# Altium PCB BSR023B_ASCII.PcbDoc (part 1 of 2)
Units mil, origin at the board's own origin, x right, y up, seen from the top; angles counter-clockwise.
Board outline 3000 x 3000 mil, 4 copper layers (Top Layer, MidLayer 1, Mid Layer 2, Bottom Layer), stack 59.2 mil thick; 96 components, 24 nets, 183 pads, 215 vias.
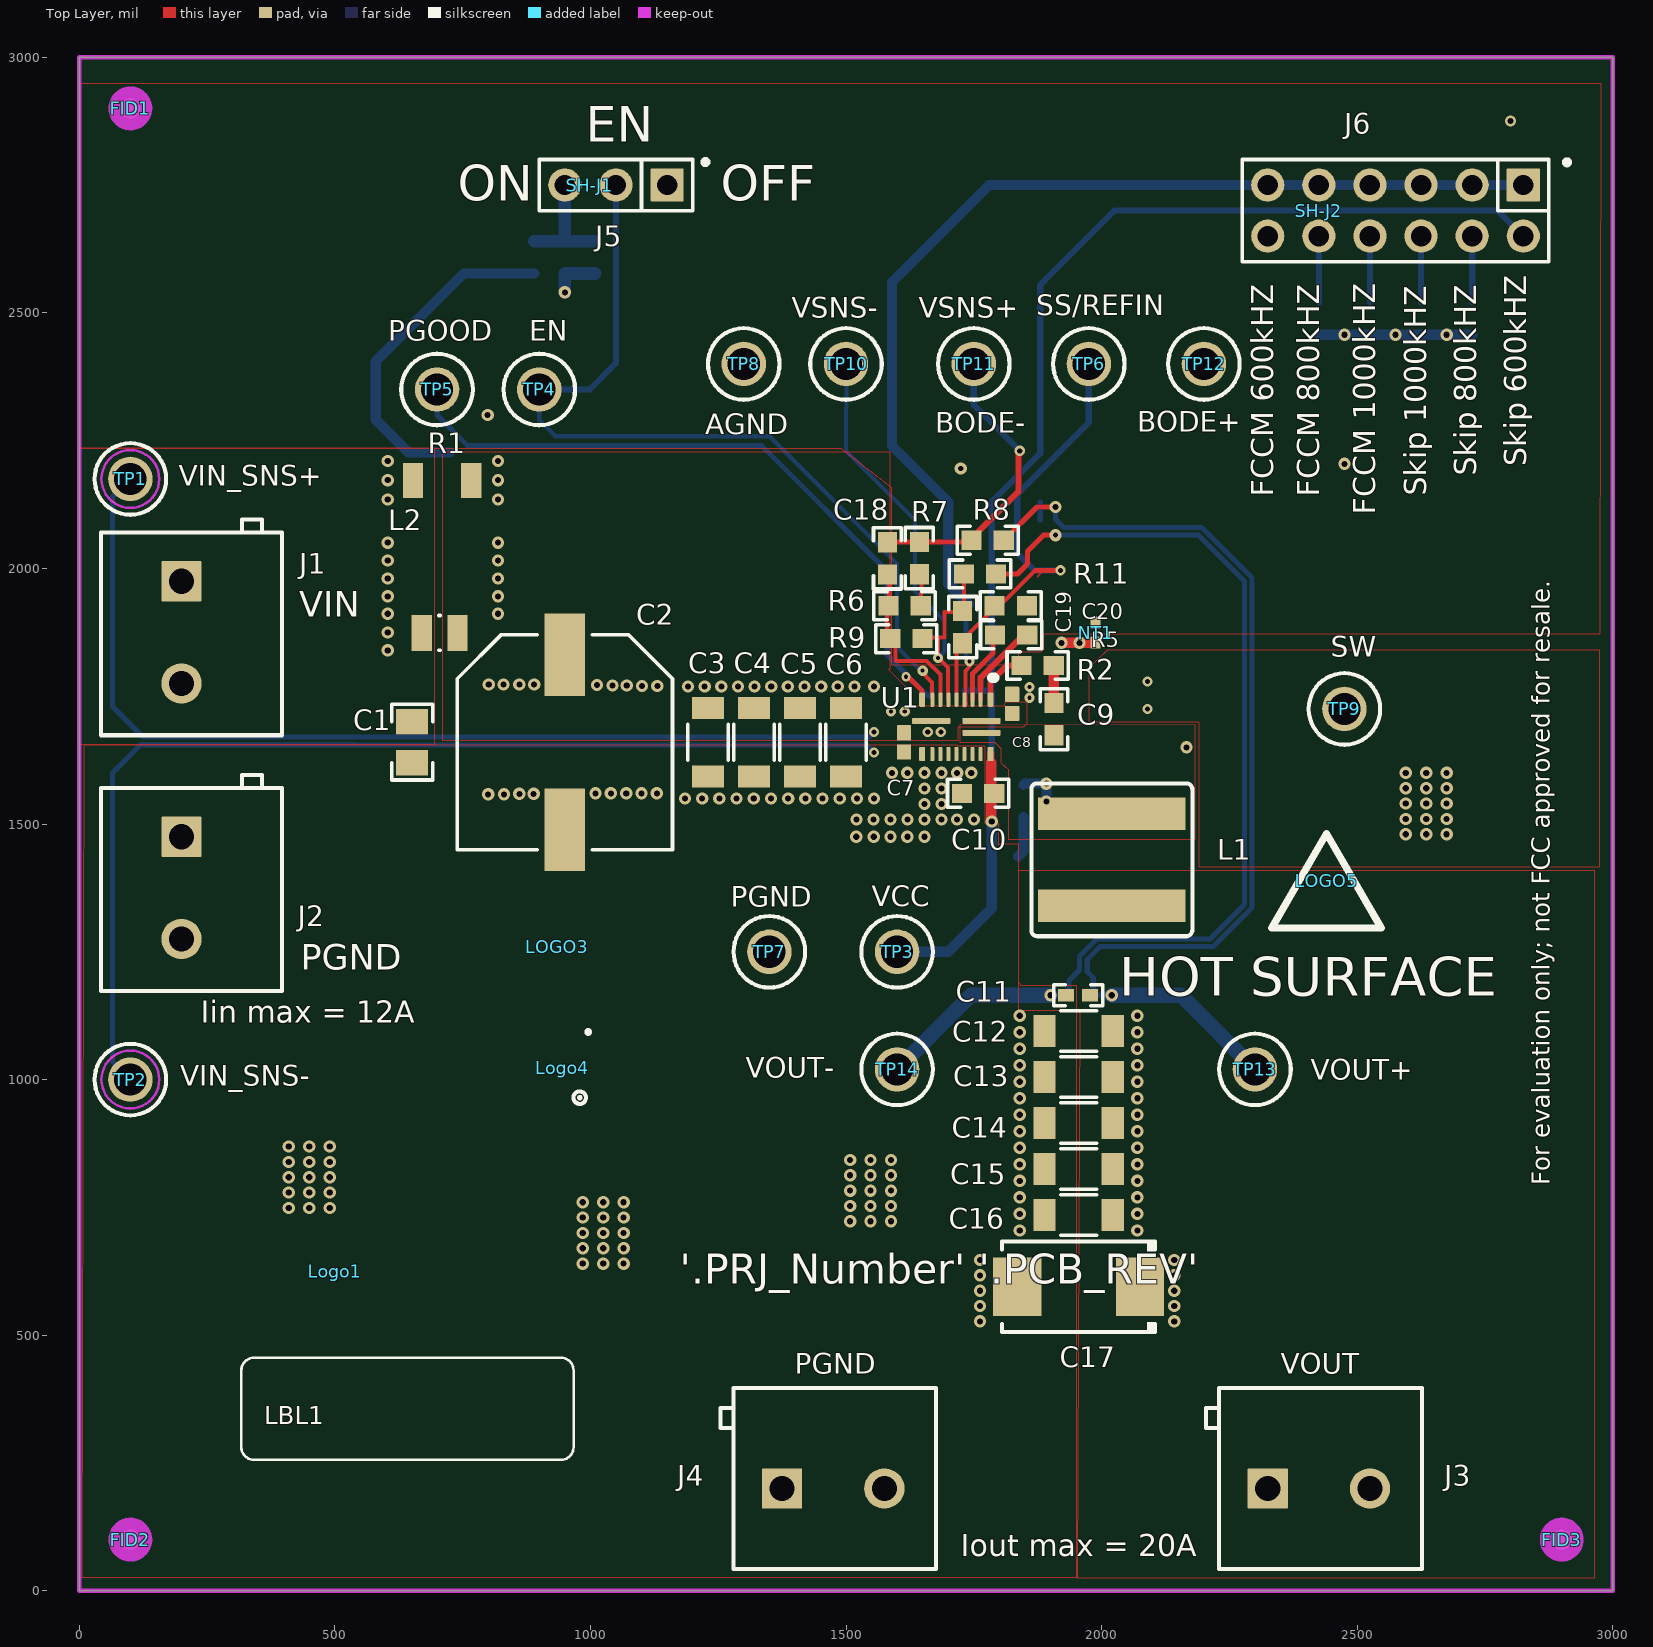
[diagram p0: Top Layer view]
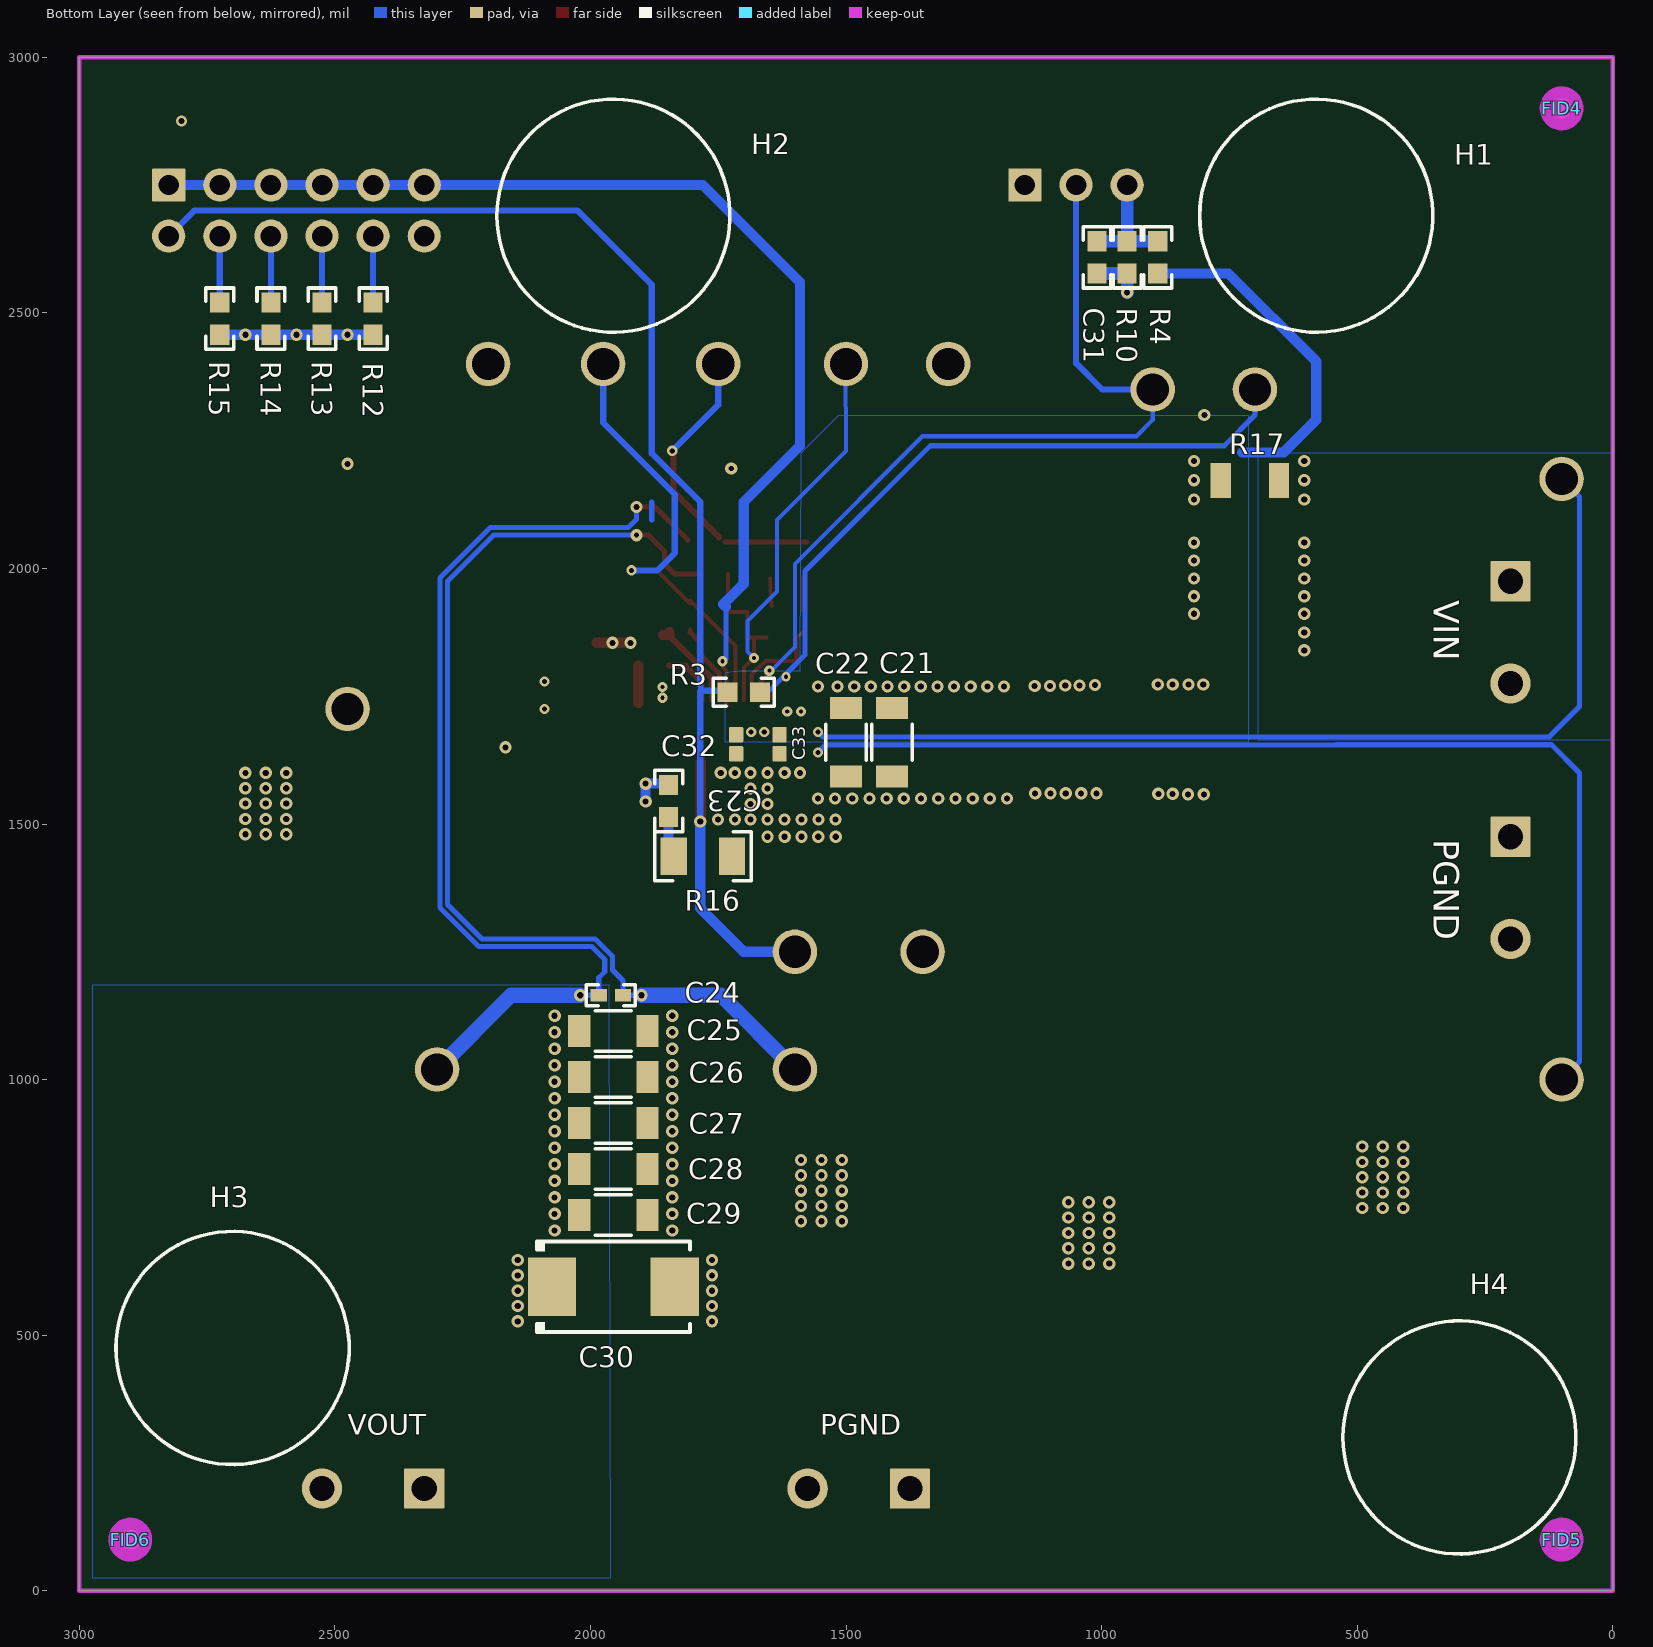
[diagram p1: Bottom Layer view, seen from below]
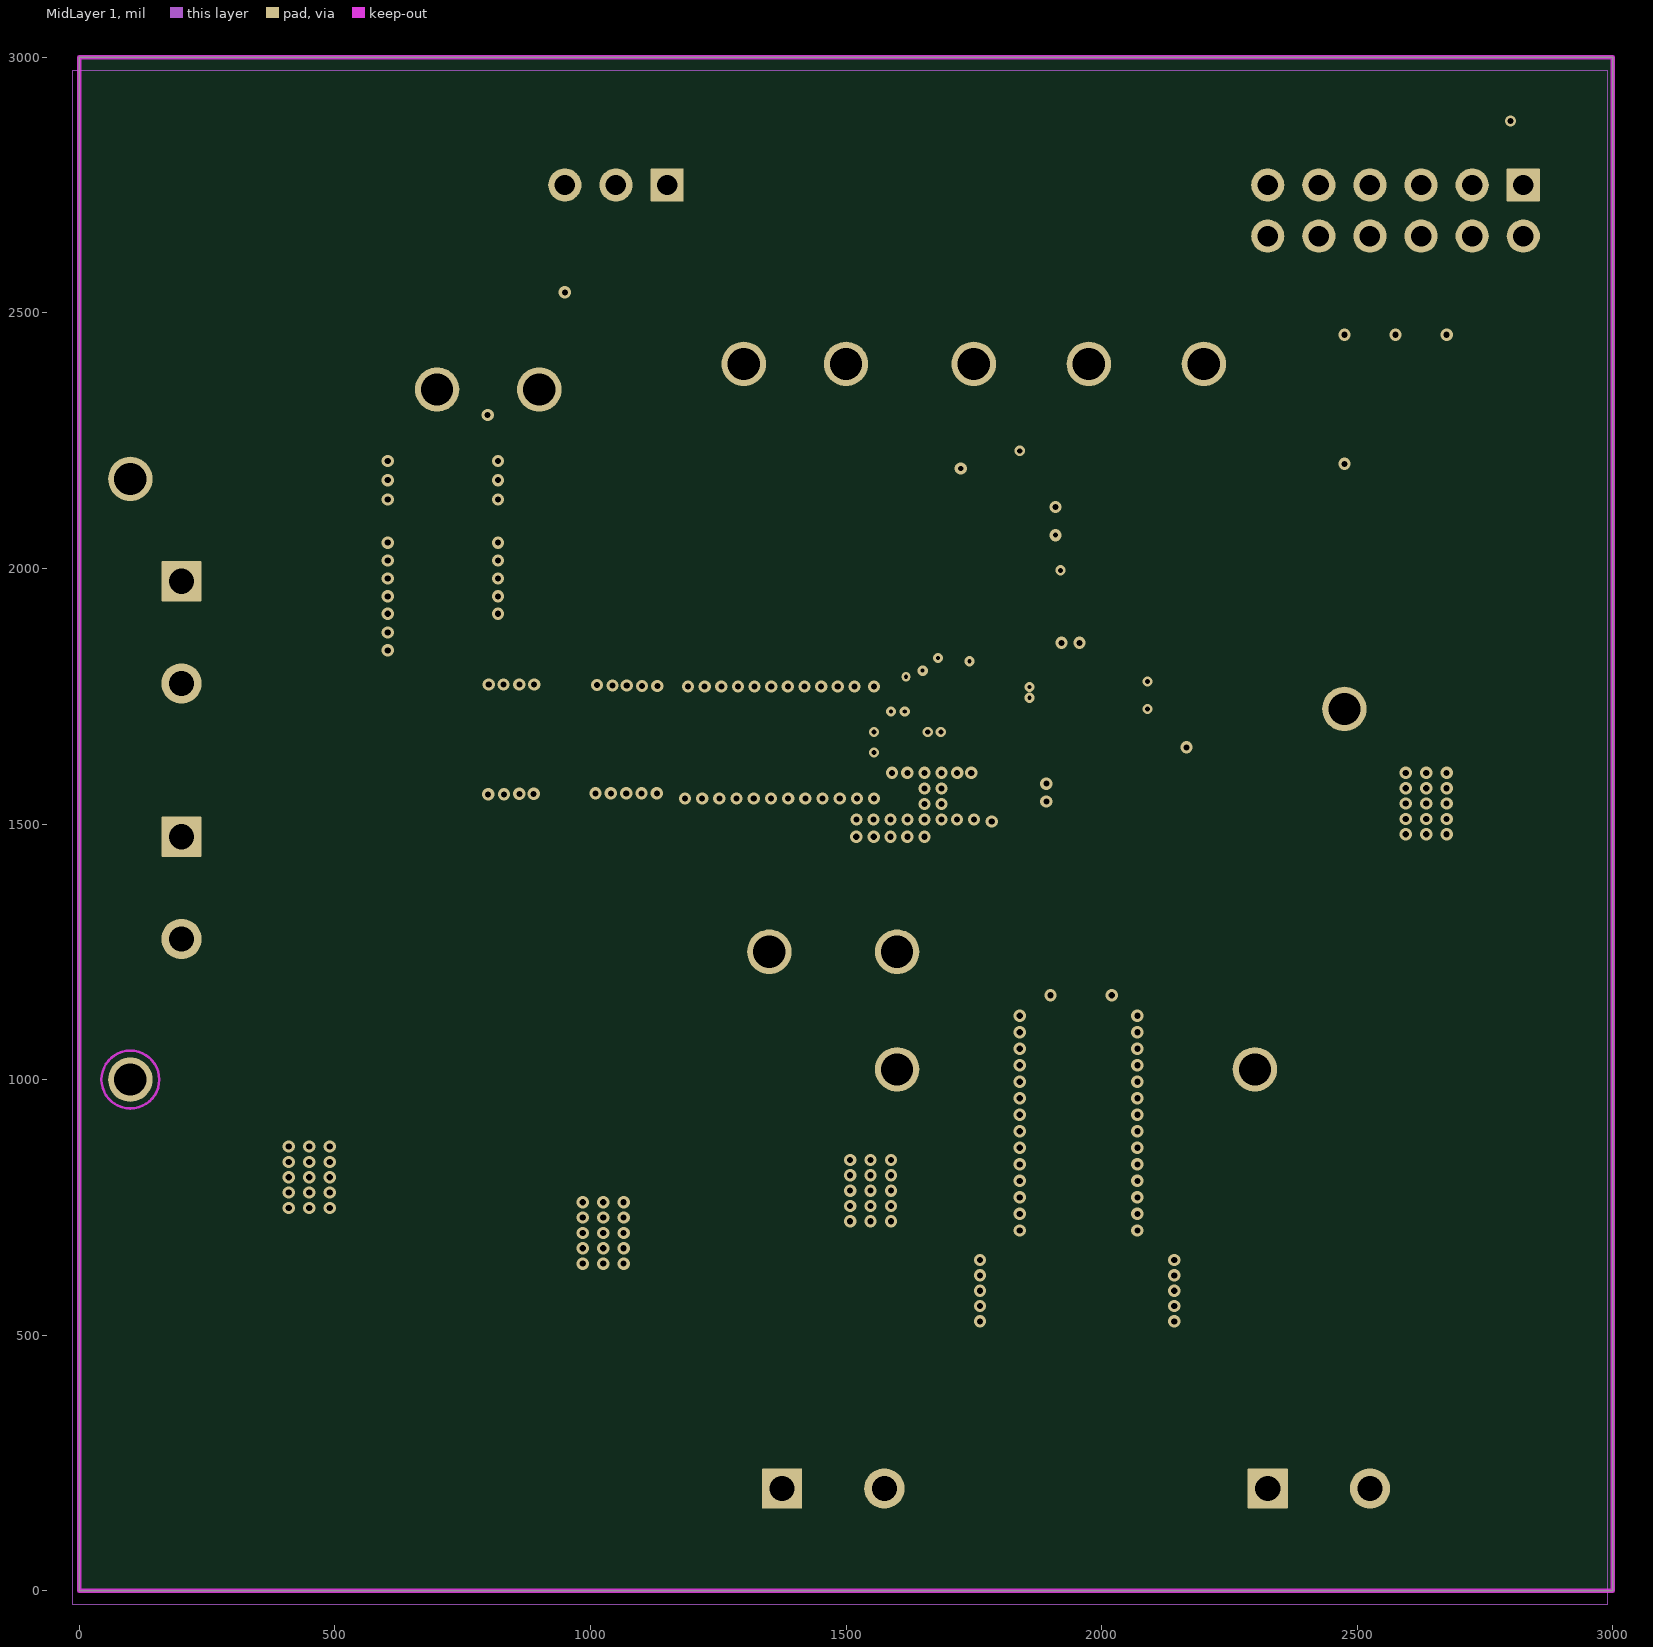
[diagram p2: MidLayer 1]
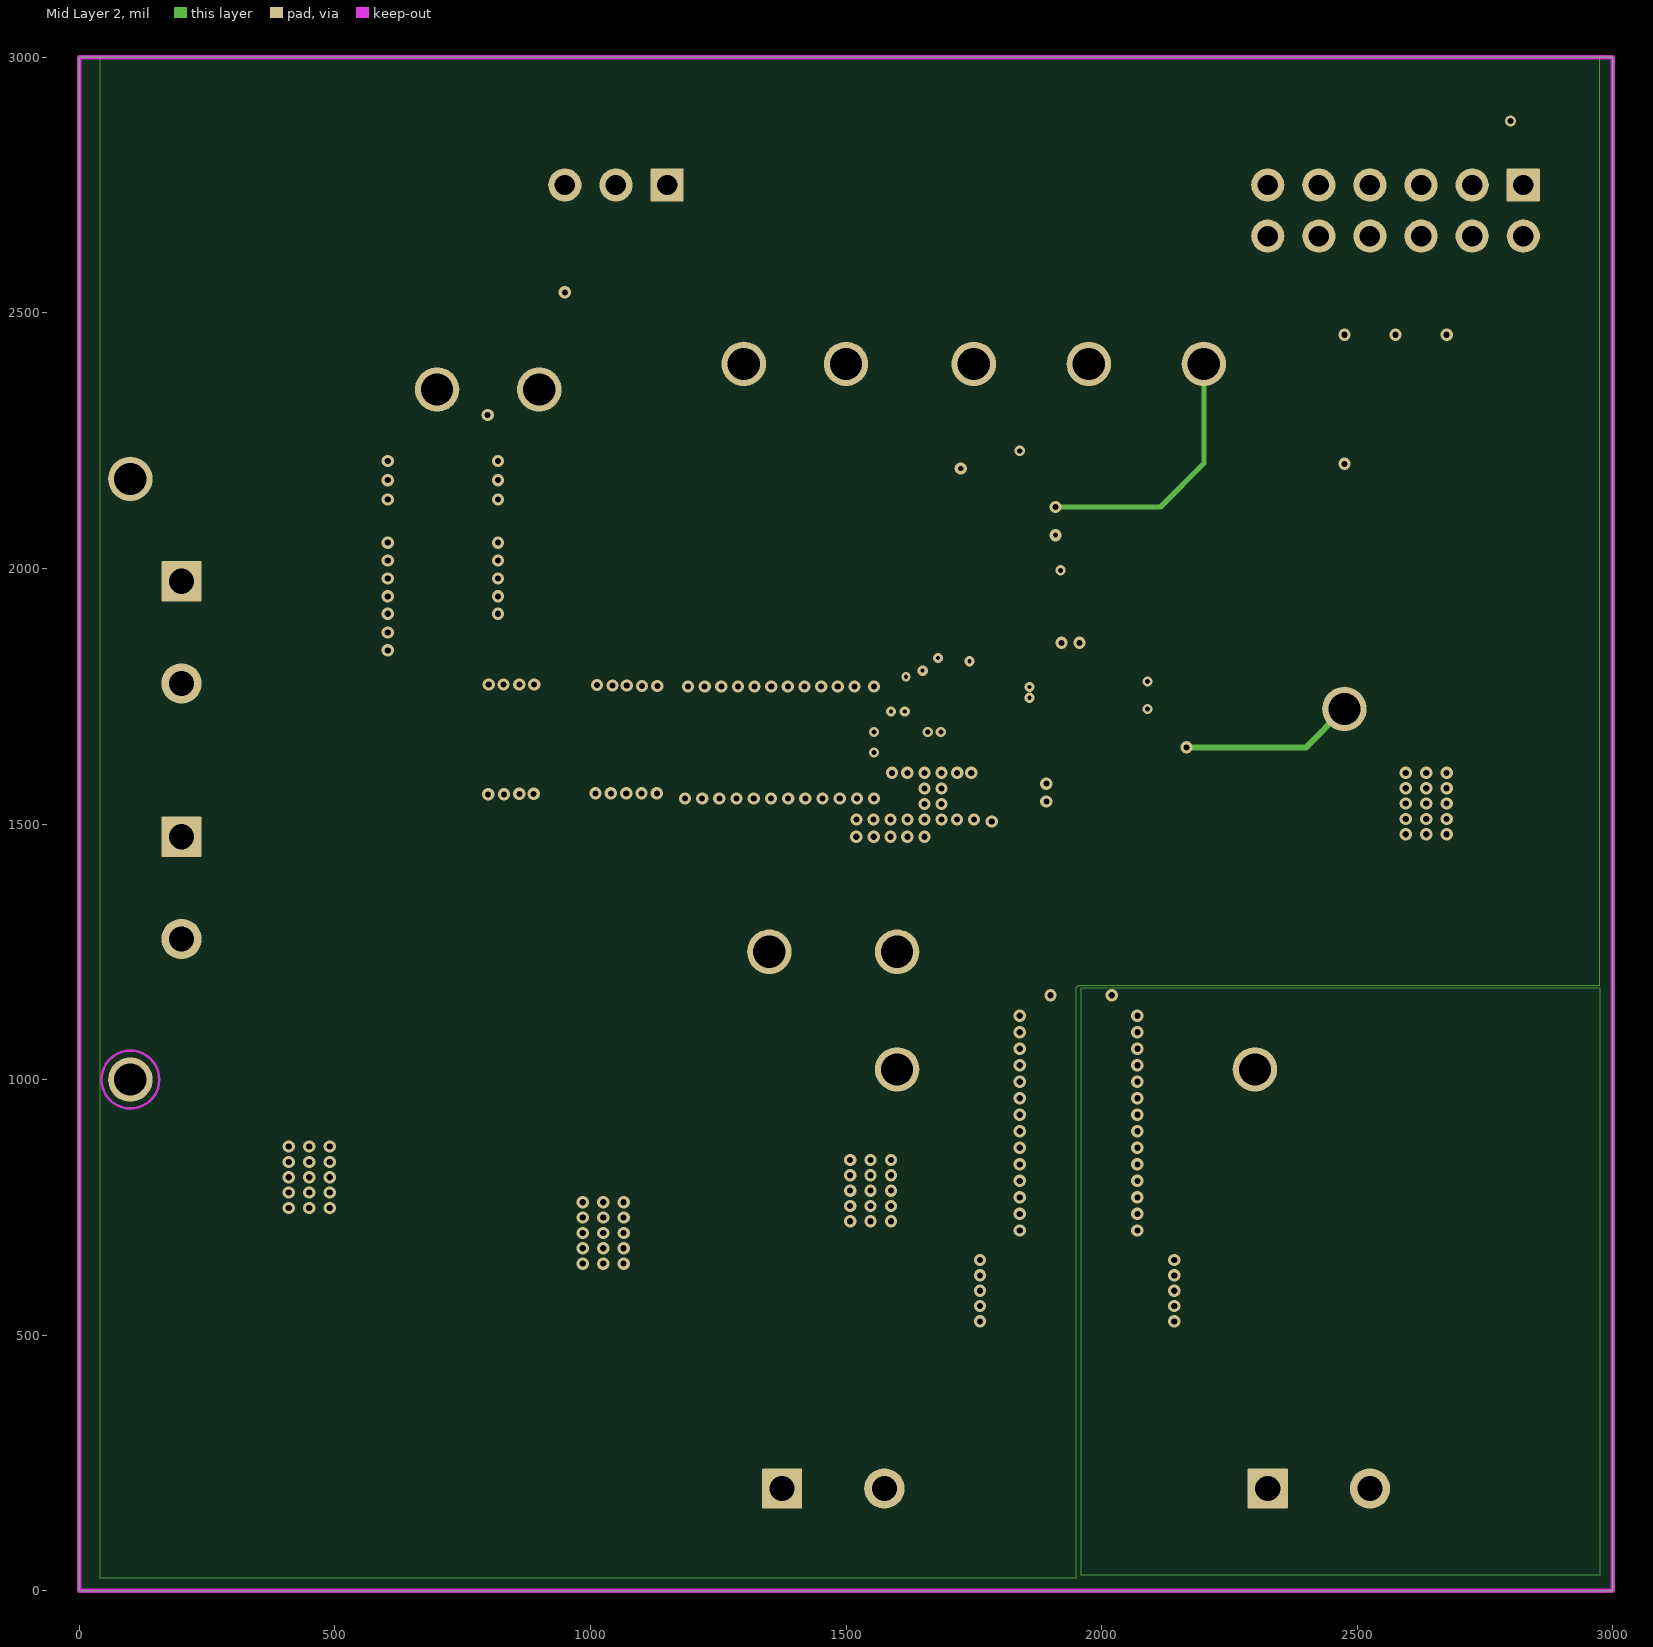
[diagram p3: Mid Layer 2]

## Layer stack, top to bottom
Top Solder: solder mask 0.4, Solder Resist, Dk 3.5
Top Layer: signal copper 2.4
Dielectric1: prepreg 9.3, FR-4 High TG, Dk 4.2
MidLayer 1: signal copper 2.4
Dielectric 3: core 31, FR-4 High TG, Dk 4.2
Mid Layer 2: signal copper 2.4
Dielectric 2: prepreg 9.3, FR-4 High TG, Dk 4.2
Bottom Layer: signal copper 2.4
Bottom Solder: solder mask 0.4, Solder Resist, Dk 3.5

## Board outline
0,0 0,3000 3000,3000 3000,0

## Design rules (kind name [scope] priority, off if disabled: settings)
AcuteAngle [All] p0: scope1count=1 scope1_0_kind=Board scope1_0_value=Board scope2count=1 scope2_0_kind=Board scope2_0_value=Board commentlength=0 minimum=4.50000000000000E+0001
AcuteAngle [All] p1: minimum=4.50000000000000E+0001 checktracksonly=FALSE
AssemblyTestPointUsage [All] p0: scope1count=1 scope1_0_kind=Board scope1_0_value=Board scope2count=1 scope2_0_kind=Board scope2_0_value=Board commentlength=0
AssemblyTestPointUsage [All] p1: valid=2
AssemblyTestpoint [All] p0: scope1count=1 scope1_0_kind=Board scope1_0_value=Board scope2count=1 scope2_0_kind=Board scope2_0_value=Board commentlength=0
BoardOutlineClearance [All] p0 off: scope1count=1 scope1_0_kind=Board scope1_0_value=Board scope2count=1 scope2_0_kind=Board scope2_0_value=Board commentlength=157 gap=40 // Protel DXP Scope 1 Expression Was: OnCopper and Not InComponentClass('Logo') and not InComponentClass('FiducialMark') and not InRegion(1000,500,4000,800)
BoardOutlineClearance BoardOutlineClearance_Poly [All] p0 off: scope1count=1 scope1_0_kind=Board scope1_0_value=Board scope2count=1 scope2_0_kind=Board scope2_0_value=Board commentlength=58 gap=25 // Protel DXP Scope 1 Expression Was: OnCopper and InPoly
BoardOutlineClearance BoardOutlineClearance_MountingHoles [All] p0 off: scope1count=1 scope1_0_kind=Board scope1_0_value=Board scope2count=1 scope2_0_kind=Board scope2_0_value=Board commentlength=86 gap=40 // Protel DXP Scope 1 Expression Was: OnCopper and InComponentClass('Mounting Holes')
BoardOutlineClearance BoardOutlineClearance_MountingHoles [OnCopper and InComponentClass('Mounting Holes')] p1: gap=40 ignorepadtopadclearanceinfootprint=FALSE
BoardOutlineClearance BoardOutlineClearance_Poly [OnCopper and InPoly] p2: gap=25 ignorepadtopadclearanceinfootprint=FALSE
BoardOutlineClearance [OnCopper and Not InComponentClass('Logo') and not InComponentClass('FiducialMark') and not InRegion(1000,500,4000,800)] p3: gap=40 ignorepadtopadclearanceinfootprint=FALSE
Clearance Clearance_Fiducial [All] p0 off: scope1count=1 scope1_0_kind=Board scope1_0_value=Board scope2count=1 scope2_0_kind=Board scope2_0_value=Board commentlength=83 gap=0 // Protel DXP Scope 1 Expression Was: (InComponentClass('FiducialMark') AND IsArc)
Clearance [All] p0: scope1count=1 scope1_0_kind=Board scope1_0_value=Board scope2count=1 scope2_0_kind=Board scope2_0_value=Board commentlength=0 gap=5
Clearance Clearance_Poly [All] p0 off: scope1count=1 scope1_0_kind=Board scope1_0_value=Board scope2count=1 scope2_0_kind=Board scope2_0_value=Board commentlength=48 gap=8 // Protel DXP Scope 1 Expression Was: InPolygon
Clearance Clearance_Keepouts [All] p0 off: scope1count=1 scope1_0_kind=Board scope1_0_value=Board scope2count=1 scope2_0_kind=Board scope2_0_value=Board commentlength=99 gap=0 // Protel DXP Scope 2 Expression Was: ((IsTrack Or IsArc) And Not InPoly) And IsFree and IsKeepOut
Clearance Clearance_Fiducial [(InComponentClass('FiducialMark') AND IsArc)] p1: gap=0 ignorepadtopadclearanceinfootprint=TRUE
Clearance Clearance_Keepouts [((IsTrack Or IsArc) And Not InPoly) And IsFree and IsKeepOut vs ((IsTrack Or IsArc) And Not InPoly) And IsFree and IsKeepOut] p2: gap=0 ignorepadtopadclearanceinfootprint=FALSE
Clearance Clearance_Poly [InPolygon] p3: gap=8 ignorepadtopadclearanceinfootprint=FALSE except(0: Arc-Hole Track-Hole SMDPad-Hole THPad-Hole Via-Hole Fill-Hole Poly-Hole Region-Hole Text-Hole)
Clearance [All] p4: gap=5 ignorepadtopadclearanceinfootprint=TRUE
ComponentClearance ComponentClearance_U1 [All] p0: scope1count=1 scope1_0_kind=Component scope1_0_value=U1 scope2count=1 scope2_0_kind=Board scope2_0_value=Board commentlength=0 gap=3 collisioncheckmode=3
ComponentClearance [All] p0 off: scope1count=1 scope1_0_kind=Board scope1_0_value=Board scope2count=1 scope2_0_kind=Board scope2_0_value=Board commentlength=0 gap=8 collisioncheckmode=3
ComponentClearance ComponentClearance_THtoTH [All] p0 off: scope1count=1 scope1_0_kind=Board scope1_0_value=Board scope2count=1 scope2_0_kind=Board scope2_0_value=Board commentlength=54 gap=10 collisioncheckmode=3 // Protel DXP Scope 2 Expression Was: IsThruComponent
ComponentClearance ComponentClearance_THtoSMT [All] p0 off: scope1count=1 scope1_0_kind=Board scope1_0_value=Board scope2count=1 scope2_0_kind=Board scope2_0_value=Board commentlength=53 gap=10 collisioncheckmode=3 // Protel DXP Scope 2 Expression Was: IsSMTComponent
ComponentClearance ComponentClearance_SmallPassives [All] p0 off: scope1count=1 scope1_0_kind=Board scope1_0_value=Board scope2count=1 scope2_0_kind=Board scope2_0_value=Board commentlength=508 gap=5 collisioncheckmode=3 // Protel DXP Scope 2 Expression Was: HasFootprint('0201*') or HasFootprint('0402*') or HasFootprint('0508') or HasFootprint('0603*') or HasFootprint('0612') or HasFootprint('0805*') or HasFootprint('0815*') or HasFootprint('0830*') or HasFootprint('1206*') or HasFootprint('1210*') or HasFootprint('1808*') or HasFootprint('1812*') or HasFootprint('1825*') or HasFootprint('2010*') or HasFootprint('2220*') or HasFootprint('2225*') or HasFootprint('2512*') or HasFootprint('2728*') or HasFootprint('3518*')
ComponentClearance ComponentClearance_MountingHoles [All] p0: scope1count=1 scope1_0_kind=ComponentClass scope1_0_value="Mounting Holes" scope2count=1 scope2_0_kind=Board scope2_0_value=Board commentlength=0 gap=250 collisioncheckmode=3
ComponentClearance ComponentClearance_ScrewToNut [All] p0 off: scope1count=1 scope1_0_kind=Board scope1_0_value=Board scope2count=1 scope2_0_kind=Board scope2_0_value=Board commentlength=71 gap=5 collisioncheckmode=3 // Protel DXP Scope 2 Expression Was: (HasFootprint('Keystone_1902C'))
ComponentClearance ComponentClearance_Logo [All] p0: scope1count=1 scope1_0_kind=ComponentClass scope1_0_value=Logo scope2count=1 scope2_0_kind=Board scope2_0_value=Board commentlength=0 gap=50 collisioncheckmode=3
ComponentClearance ComponentClearance_Shunt [All] p0: scope1count=1 scope1_0_kind=ComponentClass scope1_0_value=Header scope2count=1 scope2_0_kind=ComponentClass scope2_0_value=Shunt commentlength=0 gap=0 collisioncheckmode=3
ComponentClearance ComponentClearance_MountingHoles_FiducialMarks [All] p0: scope1count=1 scope1_0_kind=ComponentClass scope1_0_value="Mounting Holes" scope2count=1 scope2_0_kind=ComponentClass scope2_0_value=FiducialMark commentlength=0 gap=50 collisioncheckmode=3
ComponentClearance ComponentClearance_U1 [InComponent('U1')] p1: gap=3 collisioncheckmode=3 verticalgap=3 showdistances=FALSE
ComponentClearance ComponentClearance_MountingHoles_FiducialMarks [InComponentClass('Mounting Holes') vs InComponentClass('FiducialMark')] p2: gap=50 collisioncheckmode=3 verticalgap=8 showdistances=TRUE
ComponentClearance ComponentClearance_Shunt [InComponentClass('Header') vs InComponentClass('Shunt')] p3: gap=0 collisioncheckmode=3 verticalgap=0 showdistances=FALSE
ComponentClearance ComponentClearance_Logo [InComponentClass('Logo')] p4: gap=50 collisioncheckmode=3 verticalgap=10 showdistances=FALSE
ComponentClearance ComponentClearance_ScrewToNut [(HasFootprint('NY PMS 440 0025 PH')) vs (HasFootprint('Keystone_1902C'))] p5: gap=5 collisioncheckmode=3 verticalgap=10 showdistances=FALSE
ComponentClearance ComponentClearance_MountingHoles [InComponentClass('Mounting Holes')] p6: gap=250 collisioncheckmode=3 verticalgap=100000 showdistances=FALSE
ComponentClearance ComponentClearance_SmallPassives [HasFootprint('0201*') or HasFootprint('0402*') or HasFootprint('0508') or HasFootprint('0603*') or HasFootprint('0612') or HasFootprint('0805*') or HasFootprint('0815*') or HasFootprint('0830*') or HasFootprint('1206*') or HasFootprint('1210*') or HasFootprint('1808*') or HasFootprint('1812*') or HasFootprint('1825*') or HasFootprint('2010*') or HasFootprint('2220*') or HasFootprint('2225*') or HasFootprint('2512*') or HasFootprint('2728*') or HasFootprint('3518*') vs HasFootprint('0201*') or HasFootprint('0402*') or HasFootprint('0508') or HasFootprint('0603*') or HasFootprint('0612') or HasFootprint('0805*') or HasFootprint('0815*') or HasFootprint('0830*') or HasFootprint('1206*') or HasFootprint('1210*') or HasFootprint('1808*') or HasFootprint('1812*') or HasFootprint('1825*') or HasFootprint('2010*') or HasFootprint('2220*') or HasFootprint('2225*') or HasFootprint('2512*') or HasFootprint('2728*') or HasFootprint('3518*')] p7: gap=5 collisioncheckmode=3 verticalgap=5 showdistances=FALSE
ComponentClearance ComponentClearance_THtoSMT [IsThruComponent vs IsSMTComponent] p8: gap=10 collisioncheckmode=3 verticalgap=10 showdistances=FALSE
ComponentClearance ComponentClearance_THtoTH [IsThruComponent vs IsThruComponent] p9: gap=10 collisioncheckmode=3 verticalgap=10 showdistances=FALSE
ComponentClearance [All] p10 off: gap=8 collisioncheckmode=3 verticalgap=8 showdistances=FALSE
DiffPairsRouting [All] p0: scope1count=1 scope1_0_kind=Board scope1_0_value=Board scope2count=1 scope2_0_kind=Board scope2_0_value=Board commentlength=0
DiffPairsRouting [All] p1: maxlimit=100 minlimit=10 mostfreqgap=10 toplayer_minwidth=15 toplayer_maxwidth=15 toplayer_prefwidth=15 midlayer1_minwidth=15 midlayer1_maxwidth=15 midlayer1_prefwidth=15 midlayer2_minwidth=15 midlayer2_maxwidth=15 midlayer2_prefwidth=15 bottomlayer_minwidth=15 bottomlayer_maxwidth=15 bottomlayer_prefwidth=15 maxuncoupledlength=1000
FabricationTestPointUsage TestPointUsage [All] p0: scope1count=1 scope1_0_kind=Board scope1_0_value=Board scope2count=1 scope2_0_kind=Board scope2_0_value=Board commentlength=0 valid=2 allowmultiple=FALSE
FabricationTestPointUsage TestPointUsage [All] p1: valid=2 allowmultiple=FALSE
FabricationTestpoint Testpoint [All] p0: scope1count=1 scope1_0_kind=Board scope1_0_value=Board scope2count=1 scope2_0_kind=Board scope2_0_value=Board commentlength=0 side=3 testpointundercomponent=TRUE minsize=40 maxsize=100 preferedsize=60 minholesize=0 maxholesize=40 preferedholesize=32 testpointgrid=1
FabricationTestpoint Testpoint [All] p1: side=3 testpointundercomponent=TRUE minsize=40 maxsize=100 preferedsize=60 minholesize=0 maxholesize=40 preferedholesize=32 testpointgrid=1 allowsidetop=TRUE allowsidebottom=TRUE usegrid=TRUE gridtolerance=0.01
FanoutControl Fanout_Small [All] p0 off: scope1count=1 scope1_0_kind=Board scope1_0_value=Board scope2count=1 scope2_0_kind=Board scope2_0_value=Board commentlength=84 // Protel DXP Scope 1 Expression Was: (CompPinCount < 5)   Fanout_Small (Default Rule)
FanoutControl Fanout_Default [All] p0: scope1count=1 scope1_0_kind=Board scope1_0_value=Board scope2count=1 scope2_0_kind=Board scope2_0_value=Board commentlength=30 // Fanout_Default (Default Rule)
FanoutControl Fanout_SOIC [All] p0 off: scope1count=1 scope1_0_kind=Board scope1_0_value=Board scope2count=1 scope2_0_kind=Board scope2_0_value=Board commentlength=71 // Protel DXP Scope 1 Expression Was: IsSOIC   Fanout_SOIC (Default Rule)
FanoutControl Fanout_BGA [All] p0 off: scope1count=1 scope1_0_kind=Board scope1_0_value=Board scope2count=1 scope2_0_kind=Board scope2_0_value=Board commentlength=69 // Protel DXP Scope 1 Expression Was: IsBGA   Fanout_BGA (Default Rule)
FanoutControl Fanout_LCC [All] p0 off: scope1count=1 scope1_0_kind=Board scope1_0_value=Board scope2count=1 scope2_0_kind=Board scope2_0_value=Board commentlength=69 // Protel DXP Scope 1 Expression Was: IsLCC   Fanout_LCC (Default Rule)
FanoutControl Fanout_LCC [IsLCC] p1: bgadir=Out bgaviamode=Centered fanoutstyle=Auto fanoutdirection=Alternating viagrid=1 // Fanout_LCC (Default Rule)
FanoutControl Fanout_BGA [IsBGA] p2: bgadir=Out bgaviamode=Centered fanoutstyle=Auto fanoutdirection=Alternating viagrid=1 // Fanout_BGA (Default Rule)
FanoutControl Fanout_Default [All] p4: bgadir=Out bgaviamode=Centered fanoutstyle=Auto fanoutdirection=Alternating viagrid=1 // Fanout_Default (Default Rule)
FanoutControl Fanout_Small [(CompPinCount < 5)] p5: bgadir=Out bgaviamode=Centered fanoutstyle=Auto fanoutdirection=OutThenIn viagrid=1 // Fanout_Small (Default Rule)
Height [All] p0: scope1count=1 scope1_0_kind=Board scope1_0_value=Board scope2count=1 scope2_0_kind=Board scope2_0_value=Board commentlength=0
HoleSize [All] p0: scope1count=1 scope1_0_kind=Board scope1_0_value=Board scope2count=1 scope2_0_kind=Board scope2_0_value=Board commentlength=0 absolutevalues=TRUE maxlimit=251 minlimit=7.87 maxpercent=80.000 minpercent=20.000
HoleSize [All] p1: absolutevalues=TRUE maxlimit=251 minlimit=7.87 maxpercent=80.000 minpercent=20.000
HoleToHoleClearance [All] p0: scope1count=1 scope1_0_kind=Board scope1_0_value=Board scope2count=1 scope2_0_kind=Board scope2_0_value=Board commentlength=0
LayerPairs [All] p0: scope1count=1 scope1_0_kind=Board scope1_0_value=Board scope2count=1 scope2_0_kind=Board scope2_0_value=Board commentlength=0 enforce=TRUE
MinimumAnnularRing [All] p0: scope1count=1 scope1_0_kind=Board scope1_0_value=Board scope2count=1 scope2_0_kind=Board scope2_0_value=Board commentlength=0 minimumring=5
MinimumAnnularRing MinimumAnnularRing_ThermalPadVias [All] p0 off: scope1count=1 scope1_0_kind=Board scope1_0_value=Board scope2count=1 scope2_0_kind=Board scope2_0_value=Board commentlength=63 minimumring=5.91 // Protel DXP Scope 1 Expression Was: IsVia and InAnyComponent
MinimumAnnularRing MinimumAnnularRing_ThermalPadVias [IsVia and InAnyComponent] p1: minimumring=5.91
MinimumAnnularRing [All] p2: minimumring=5
MinimumSolderMaskSliver [All] p0: scope1count=1 scope1_0_kind=Board scope1_0_value=Board scope2count=1 scope2_0_kind=Board scope2_0_value=Board commentlength=0
MinimumSolderMaskSliver MinimumSolderMaskSliver_Logo [All] p0: scope1count=1 scope1_0_kind=ComponentClass scope1_0_value=Logo scope2count=1 scope2_0_kind=ComponentClass scope2_0_value=Logo commentlength=0
MinimumSolderMaskSliver MinimumSolderMaskSliver_Logo [InComponentClass('Logo') vs InComponentClass('Logo')] p1: minsoldermaskwidth=0.7
MinimumSolderMaskSliver [All] p2: minsoldermaskwidth=2
NetAntennae [All] p0: scope1count=1 scope1_0_kind=Board scope1_0_value=Board scope2count=1 scope2_0_kind=Board scope2_0_value=Board commentlength=0
PasteMaskExpansion [All] p0: scope1count=1 scope1_0_kind=Board scope1_0_value=Board scope2count=1 scope2_0_kind=Board scope2_0_value=Board commentlength=0 expansion=0
PlaneClearance [All] p0: scope1count=1 scope1_0_kind=Board scope1_0_value=Board scope2count=1 scope2_0_kind=Board scope2_0_value=Board commentlength=0 clearance=20
PlaneConnect [All] p0: scope1count=1 scope1_0_kind=Board scope1_0_value=Board scope2count=1 scope2_0_kind=Board scope2_0_value=Board commentlength=0 planeconnectstyle=Relief reliefexpansion=10 reliefentries=4 reliefconductorwidth=10 reliefairgap=10
PlaneConnect [All] p1: planeconnectstyle=Relief reliefexpansion=10 reliefentries=4 reliefconductorwidth=10 reliefairgap=10
PolygonConnect [All] p0: scope1count=1 scope1_0_kind=Board scope1_0_value=Board scope2count=1 scope2_0_kind=Board scope2_0_value=Board commentlength=0 connectstyle=Direct reliefconductorwidth=10 reliefentries=4 polygonreliefangle="90 Angle"
PolygonConnect [All] p1: connectstyle=Direct reliefconductorwidth=10 reliefentries=4 polygonreliefangle="90 Angle" airgapwidth=10
RoutingCorners [All] p0: scope1count=1 scope1_0_kind=Board scope1_0_value=Board scope2count=1 scope2_0_kind=Board scope2_0_value=Board commentlength=0 cornerstyle=45-Degree minsetback=100 maxsetback=100
RoutingLayers [All] p0: scope1count=1 scope1_0_kind=Board scope1_0_value=Board scope2count=1 scope2_0_kind=Board scope2_0_value=Board commentlength=0 top layer=Automatic mid layer 1=Automatic mid layer 2=Automatic bottom layer=Automatic
RoutingPriority [All] p0: scope1count=1 scope1_0_kind=Board scope1_0_value=Board scope2count=1 scope2_0_kind=Board scope2_0_value=Board commentlength=0
RoutingTopology [All] p0: scope1count=1 scope1_0_kind=Board scope1_0_value=Board scope2count=1 scope2_0_kind=Board scope2_0_value=Board commentlength=0 topology=Shortest
RoutingVias [All] p0: scope1count=1 scope1_0_kind=Board scope1_0_value=Board scope2count=1 scope2_0_kind=Board scope2_0_value=Board commentlength=0 holewidth=16 width=34 viastyle="Through Hole" minholewidth=7.87 minwidth=7 maxholewidth=40 maxwidth=65
RoutingVias ThermalPadVias [All] p0 off: scope1count=1 scope1_0_kind=Board scope1_0_value=Board scope2count=1 scope2_0_kind=Board scope2_0_value=Board commentlength=63 holewidth=7.87 width=19.68 viastyle="Through Hole" minholewidth=7.87 minwidth=19.68 maxholewidth=12.99 maxwidth=23.62 // Protel DXP Scope 1 Expression Was: IsVia and InAnyComponent
RoutingVias ThermalPadVias [IsVia and InAnyComponent] p1: holewidth=7.87 width=19.68 viastyle="Through Hole" minholewidth=7.87 minwidth=19.68 maxholewidth=12.99 maxwidth=23.62
RoutingVias [All] p2: holewidth=16 width=34 viastyle="Through Hole" minholewidth=7.87 minwidth=7 maxholewidth=40 maxwidth=65
ShortCircuit [All] p0: scope1count=1 scope1_0_kind=Board scope1_0_value=Board scope2count=1 scope2_0_kind=Board scope2_0_value=Board commentlength=0 allowed=FALSE
SilkToBoardRegionClearance [All] p0 off: scope1count=1 scope1_0_kind=Board scope1_0_value=Board scope2count=1 scope2_0_kind=Board scope2_0_value=Board commentlength=130 // Protel DXP Scope 1 Expression Was: Not ((IsComment or IsDesignator) And (Hide <> 'False')) and not InRegion(1000,500,4000,800)
SilkToBoardRegionClearance [Not ((IsComment or IsDesignator) And (Hide <> 'False')) and not InRegion(1000,500,4000,800)] p1:
SilkToSilkClearance [All] p0: scope1count=1 scope1_0_kind=Board scope1_0_value=Board scope2count=1 scope2_0_kind=Board scope2_0_value=Board commentlength=0
SilkToSilkClearance SilkToSilkClearance_Pb-FreeLogo [All] p0 off: scope1count=1 scope1_0_kind=Board scope1_0_value=Board scope2count=1 scope2_0_kind=Board scope2_0_value=Board commentlength=120 // Protel DXP Scope 2 Expression Was: (HasFootprint('Pb-Free_Overlay_Medium') OR HasFootprint('Pb-Free_Overlay_Small'))
SilkToSilkClearance SilkToSilkClearance_Pb-FreeLogo [(HasFootprint('Pb-Free_Overlay_Medium') OR HasFootprint('Pb-Free_Overlay_Small')) vs (HasFootprint('Pb-Free_Overlay_Medium') OR HasFootprint('Pb-Free_Overlay_Small'))] p1: silktosilkclearance=0
SilkToSilkClearance [All] p2: silktosilkclearance=1
SilkToSolderMaskClearance "Silk to Solder Mask Opening" [All] p0: scope1count=1 scope1_0_kind=Board scope1_0_value=Board scope2count=1 scope2_0_kind=Board scope2_0_value=Board commentlength=0
SilkToSolderMaskClearance SilkToComponentPadClearance [All] p0 off: scope1count=1 scope1_0_kind=Board scope1_0_value=Board scope2count=1 scope2_0_kind=Board scope2_0_value=Board commentlength=63 // Protel DXP Scope 1 Expression Was: IsPad and InAnycomponent
SilkToSolderMaskClearance SilkToComponentPadClearance [IsPad and InAnycomponent] p1: minsilkscreentomaskgap=0 clearancetoexposedcopper=TRUE
SilkToSolderMaskClearance "Silk to Solder Mask Opening" [All] p2: minsilkscreentomaskgap=0 clearancetoexposedcopper=FALSE
SolderMaskExpansion [All] p0: scope1count=1 scope1_0_kind=Board scope1_0_value=Board scope2count=1 scope2_0_kind=Board scope2_0_value=Board commentlength=0 expansion=1.97
SolderMaskExpansion [All] p1: expansion=1.97
UnRoutedNet [All] p0: scope1count=1 scope1_0_kind=Board scope1_0_value=Board scope2count=1 scope2_0_kind=Board scope2_0_value=Board commentlength=0
UnpouredPolygon [All] p0: scope1count=1 scope1_0_kind=Board scope1_0_value=Board scope2count=1 scope2_0_kind=Board scope2_0_value=Board commentlength=0
Width [All] p0: scope1count=1 scope1_0_kind=Board scope1_0_value=Board scope2count=1 scope2_0_kind=Board scope2_0_value=Board commentlength=0 maxlimit=100 minlimit=6 preferedwidth=10
Width [All] p1: maxlimit=100 minlimit=6 preferedwidth=10 checkconnectedcopper=TRUE
15 further rules are at their usual default settings.

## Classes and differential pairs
component class AssemblyNote: ZZ1 ZZ2 ZZ3 ZZ4
component class Shunt: SH-J1 SH-J2
component class Logo: Logo1
component class BSR023A_Hardware: FID1 FID2 FID3 FID4 FID5 FID6 H1 H2 H3 H4 LBL1 Logo1 Logo2 LOGO3 Logo4 LOGO5 Logo? LOGO? SH-J1 SH-J2 ZZ1 ZZ2 ZZ3 ZZ4
component class FiducialMark: FID1 FID2 FID3 FID4 FID5 FID6
component class Label: LBL1
component class Header: J5 J6
component class BSR023A: C1 C2 C3 C4 C5 C6 C7 C8 C9 C10 C11 C12 C13 C14 C15 C16 C17 C18 C19 C20 C21 C22 C23 C24 C25 C26 C27 C28 C29 C30 C31 C32 C33 C41 C42 J1 J2 J3 J4 J5 J6 L1 L2 NT1 PGND PGND2 PGND3 "PGND 1" "PGND 2" R1 R2 R3 R4 R5 R6 R7 R8 R9 R10 R11 R12 R13 R14 R15 R16 R17 TP1 TP2 TP3 TP4 TP5 TP6 TP7 TP8 TP9 TP10 TP11 TP12 TP13 TP14 U1 VOUT VOUT2 Vout-

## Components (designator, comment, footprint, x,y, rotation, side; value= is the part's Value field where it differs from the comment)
C1 "GRM21BZ71E106KE15L" 0805_HV 651.23,1660 r270 top
C2 "EEE-FC1E331P" SM_RADIAL_G 950,1660 r270 top
C3 "GRM31CC81E226ME11L" 1206_190 1230,1660 r270 top
C4 "GRM31CC81E226ME11L" 1206_190 1320,1660 r270 top
C5 "GRM31CC81E226ME11L" 1206_190 1410,1660 r270 top
C6 "GRM31CC81E226ME11L" 1206_190 1500,1660 r270 top
C7 "1uF" FP-GRM155C81E105KE11D_0402-IPC_A 1613.44,1659.71 r270 top
C8 "1uF" FP-GRM155C81E105KE11D_0402-IPC_A 1825,1735 r90 top
C9 "CGA3E2X7R1H104K080AA" 0603 1907,1705 r90 top
C10 "GRM188R71A225KE15D" 0603 1758.51,1560 r180 top
C11 "GRM155R70J104KA01D" 0402 1954,1165 r180 top
C12 "GRM31CC80J476KE18L" 1206_180 1955,1095 r180 top
C13 "GRM31CC80J476KE18L" 1206_180 1955,1005 r180 top
C14 "GRM31CC80J476KE18L" 1206_180 1955,915 r180 top
C15 "GRM31CC80J476KE18L" 1206_180 1955,825 r180 top
C16 "GRM31CC80J476KE18L" 1206_180 1955,735 r180 top
C17 "6TPF470MAH" 7343-40 1955,595 r180 top
C18 "C0603X222K5RACTU" 0603 1581.03,2019.76 r270 top
C19 "C1608X7R1C224K080AC" 0603 1728.26,1885 r90 top
C20 "C0603C223K4RACTU" 0603 1822.24,1927 r0 top
C21 "GRM31CC81E226ME11L" 1206_190 1410,1660 r270 bottom
C22 "GRM31CC81E226ME11L" 1206_190 1500,1660 r270 bottom
C23 "CL10C102JB8NNNC" 0603 1847,1545 r270 bottom
C24 "GRM155R70J104KA01D" 0402 1960,1165 r180 bottom
C25 "GRM31CC80J476KE18L" 1206_180 1955,1095 r180 bottom
C26 "GRM31CC80J476KE18L" 1206_180 1955,1005 r180 bottom
C27 "GRM31CC80J476KE18L" 1206_180 1955,915 r180 bottom
C28 "GRM31CC80J476KE18L" 1206_180 1955,825 r180 bottom
C29 "GRM31CC80J476KE18L" 1206_180 1955,735 r180 bottom
C30 "6TPF470MAH" 7343-40 1955,595 r180 bottom
C31 "885012206040" 0603 1008.9,2608.5 r270 bottom
C32 "1uF" FP-GRM155C81E105KE11D_0402-IPC_A 1715,1656 r270 bottom
C33 "1uF" FP-GRM155C81E105KE11D_0402-IPC_A 1630,1656 r270 bottom
FID1 "Fiducial" Fiducial10-20 100,2900 r0 top
FID2 "Fiducial" Fiducial10-20 100,100 r0 top
FID3 "Fiducial" Fiducial10-20 2900,100 r0 top
FID4 "Fiducial" Fiducial10-20 100,2900 r180 bottom
FID5 "Fiducial" Fiducial10-20 100,100 r180 bottom
FID6 "Fiducial" Fiducial10-20 2900,100 r180 bottom
H1 "SJ-5303 (CLEAR)" Bumpon_SJ5003Transparent 580,2690 r90 bottom
H2 "SJ-5303 (CLEAR)" Bumpon_SJ5003Transparent 1955,2690 r90 bottom
H3 "SJ-5303 (CLEAR)" Bumpon_SJ5003Transparent 2700,475 r90 bottom
H4 "SJ-5303 (CLEAR)" Bumpon_SJ5003Transparent 300,300 r90 bottom
J1 "ED120/2DS" On-Shore_ED120_2DS 200,1875 r270 top
J2 "ED120/2DS" On-Shore_ED120_2DS 200,1375 r270 top
J3 "ED120/2DS" On-Shore_ED120_2DS 2425,200 r0 top
J4 "ED120/2DS" On-Shore_ED120_2DS 1475,200 r0 top
J5 "" Samtec_HTSW-103-07-G-S 1050,2750 r180 top
J6 "TSW-106-07-G-D" TSW-106-07-G-D 2575,2700 r180 top
L1 "XAL7070-551MEB" XAL7070 2020,1430 r270 top
L2 "L_Filt" 0805CS 705,1873.91 r0 top
LBL1 "THT-14-423-10" Label_650x200 642.13,356 r0 top
Logo1 "Texas Instruments" TI_Stacked_Overlay_Small 500,625 r0 top
Logo2 "FCC disclaimer" FCC_disclaimer 4416,4871 r90 top
LOGO3 "CE Mark" CE_Mark_5mm 935,1260 r0 top
Logo4 "WEEE logo" WEEE_Minimum 945,1022.98 r0 top
LOGO5 "CAUTION HOT SURFACE" IEC_HotSurface_Small 2440,1389.36 r0 top
NT1 "Net-Tie" NetTie_0402 1988.34,1874.38 r270 top net-tie
R1 "5108" 5108 710,2172 r0 top
R2 "RMCF0603ZT0R00" 0603 1875,1810 r0 top
R3 "CRCW060330K1FKEA" 0603 1700.07,1757.8 r180 bottom
R4 "RT0603BRD0720KL" 0603 890.13,2608.5 r270 bottom
R5 "CRCW06036K04FKEA" 0603 1823.04,1870 r180 top
R6 "CRCW060318K7FKEA" 0603 1614.64,1927 r0 top
R7 "RMCF0603ZT0R00" 0603 1643.58,2020 r90 top
R8 "CRCW060310R0FKEA" 0603 1777.21,2055 r180 top
R9 "CRCW060310K0FKEA" 0603 1617.94,1862.57 r0 top
R10 "CRCW060310K0FKEA" 0603 950,2608.5 r90 bottom
R11 "RMCF0603ZT0R00" 0603 1762.26,1989.2 r180 top
R12 "CRCW060330K1FKEA" 0603 2425,2488.5 r90 bottom
R13 "RC0603FR-0760K4L" 0603 2525,2488.5 r90 bottom
R14 "RC0603FR-07121KL" 0603 2625,2488.5 r90 bottom
R15 "CRCW0603243KFKEA" 0603 2725,2488.5 r270 bottom
R16 "CRM1206-JW-2R2ELF" 1206 1780,1437 r0 bottom
R17 "5108" 5108 710,2172 r0 bottom
SH-J1 "SNT-100-BK-G" SNT-100-BK-G 998.8,2750 r180 top
SH-J2 "SNT-100-BK-G" SNT-100-BK-G 2425,2700 r90 top
TP1 "VIN_SNS+" Keystone5010 100,2175 r90 top
TP2 "VIN_SNS-" Keystone5011 100,1000 r90 top
TP3 "VCC" Keystone5010 1600,1250 r90 top
TP4 "EN" Keystone5009 900,2350 r0 top
TP5 "PGOOD" Keystone5009 700,2350 r180 top
TP6 "SS/REFIN" Keystone5009 1975,2400 r180 top
TP7 "PGND" Keystone5011 1350,1250 r90 top
TP8 "AGND" Keystone5011 1300,2400 r90 top
TP9 "SW" Keystone5008 2475,1725 r90 top
TP10 "VSNS-" Keystone5013 1500,2400 r90 top
TP11 "BODE-" Keystone5013 1750,2400 r90 top
TP12 "BODE+" Keystone5013 2200,2400 r90 top
TP13 "VOUT+" Keystone5010 2300,1020 r90 top
TP14 "VOUT-" Keystone5011 1600,1020 r90 top
U1 "TPS54JB00" RWW0021A 1716,1690 r270 top
ZZ1 "This Assembly Note is for PCB labels only" AssemblyNoteLabel 635,6660 r0 top
ZZ2 "These assemblies are ESD sensitive, ESD precautions shall be observed." AssemblyNote 632,6468 r0 top
ZZ3 "These assemblies must be clean and free from flux and all contaminants. Use of no clean flux is not acceptable." AssemblyNote 637,6305 r0 top
ZZ4 "These assemblies must comply with workmanship standards IPC-A-610 Class 2, unless otherwise specified." AssemblyNote 637,6113 r0 top

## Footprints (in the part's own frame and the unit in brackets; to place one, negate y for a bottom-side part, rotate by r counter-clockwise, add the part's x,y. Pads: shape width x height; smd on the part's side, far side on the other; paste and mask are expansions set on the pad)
0402 [mm] "0402 from SM-752 data"
  rect 0.8x0.6 smd: 1(-0.6,0) 2(0.6,0)
  silkscreen extent -1.22,-0.52 1.22,0.52
0603 [mm] "0603 from SM-752 data"
  rect 1x0.95 smd: 1(-0.8,0) 2(0.8,0)
  silkscreen extent -1.52,-0.69 1.52,0.69
0805_HV [mil] "0805 with 30mil clearance between pads"
  rect 50x63 smd: 1(-40,0) 2(40,0)
  silkscreen extent -74,-40 74,40
0805CS [mil] "Coilcraft Chip Inductors - 0805CS Series (2012)"
  rect 40x70 smd: 1(-35,0) 2(35,0)
  silkscreen extent -2,-34 2,34
1206 [mm] "1206 from SM-752 data"
  rect 1.3x1.85 smd: 1(-1.45,0) 2(1.45,0)
  silkscreen extent -2.4,-1.21 2.4,1.21
1206_180 [mm] "1206_180"
  rect 1.1x1.6 smd: 1(-1.7,0) 2(1.7,0)
  silkscreen extent -0.9,-1 0.9,1
1206_190 [mm] "1206_190"
  rect 1.1x1.6 smd: 1(-1.7,0) 2(1.7,0)
  silkscreen extent -0.9,-1 0.9,1
5108 [mm] "Keystone"
  rect 1.01x1.73 smd: 1(-1.445,0) 2(1.445,0)
7343-40 [mm] "Molded, 2-Leads, Body 7.3x4.3mm, Height 4mm"
  rect 2.4x2.9 smd: 1(-3.05,0) 2(3.05,0)
  silkscreen extent -3.8,-2.25 3.8,2.25
AssemblyNote [mil] "Assembly Note"
AssemblyNoteLabel [mil] "Assembly Note for PCB Labels"
Bumpon_SJ5003Transparent [mil] "3M Hemispherical Bumpon transparent"
  round 1 on Mech4: 0(0,0)
  silkscreen extent -228,-228 228,228
CE_Mark_5mm [mil] "Minimum text height for CE Mark"
FCC_disclaimer [mil]
Fiducial10-20 [mm]
  round 1 smd mask+0: 1(0,0)
  Top Layer keep-out circle w1.178: c0,0 r0.5
FP-GRM155C81E105KE11D_0402-IPC_A [mil]
  rrect14% 29.91x28.04 smd paste+0 mask+0: 1(-18.75,0) 2(18.75,0)
IEC_HotSurface_Small [mil]
  silkscreen extent -107,-93 107,92
Keystone5008 [mil] "Keystone Compact loops"
  round 87 hole 63: 1(0,0)
  silkscreen extent -70,-70 70,70
Keystone5009 [mil] "Keystone Compact loops"
  round 87 hole 63: 1(0,0)
  silkscreen extent -70,-70 70,70
Keystone5010 [mil] "Keystone Multipurpose loops"
  round 87 hole 63: 1(0,0)
  silkscreen extent -70,-70 70,70
Keystone5011 [mil] "Keystone Multipurpose loops"
  round 87 hole 63: 1(0,0)
  silkscreen extent -70,-70 70,70
Keystone5013 [mil] "Keystone Multipurpose loops"
  round 87 hole 63: 1(0,0)
  silkscreen extent -70,-70 70,70
Label_650x200 [mil] "Thermal Transfer Label"
  round 1 on Mech13: 0(0,0)
  silkscreen extent -325,-100 325,100
NetTie_0402 [mm] "Net Tie 0402 size"
  rect 0.6x0.5 smd paste-0.5: 1(-0.5,0) 2(0.5,0)
On-Shore_ED120_2DS [mm] "ONSHORE"
  rrect5% 2x2 hole 1.25: 1(-2.54,0)
  round 2 hole 1.25: 2(2.54,0)
  silkscreen extent -5.6,-4 5.12,5
RWW0021A [mm] "VQFN-HR-21"
  rrect33% 0.7x0.3 smd: 1(-1.35,1.7) 9(-1.35,-1.7) 11(1.35,-1.7) 19(1.35,1.7)
  rrect50% 0.7x0.2 smd: 2(-1.35,1.2) 3(-1.35,0.8) 4(-1.35,0.4) 5(-1.35,0) 6(-1.35,-0.4) 7(-1.35,-0.8) 8(-1.35,-1.2) 12(1.35,-1.2) 13(1.35,-0.8) 14(1.35,-0.4) 15(1.35,0) 16(1.35,0.4) 17(1.35,0.8) 18(1.35,1.2)
  rrect33% 0.3x1.9 smd paste-1: 10(-0.3,-1.25) 20(0.3,1.25) 21(-0.3,1.25)
  rrect33% 0.3x0.85 on Top Paste: 10A(-0.3,-0.725) 10B(-0.3,-1.775) 20A(0.3,1.775) 20B(0.3,0.725) 21A(-0.3,1.775) 21B(-0.3,0.725)
Samtec_HTSW-103-07-G-S [mm] "Samtec 100mil, 1x3, 230 mil above insulator"
  rrect6% 1.65x1.65 hole 1.016: 1(-2.54,0)
  round 1.65 hole 1.016: 2(0,0) 3(2.54,0)
  silkscreen extent -4.57,-1.27 3.81,1.27
SM_RADIAL_G [mm] "10 x 10.2mm:  Panasonic G"
  rect 4.1x2 smd: 1(-4.35,0) 2(4.35,0)
  silkscreen extent -5.35,-5.35 5.35,5.35
SNT-100-BK-G [mil] "Samtec STEP model"
  round 1 on Mech3: 0(0,0)
TI_Stacked_Overlay_Small [mil]
TSW-106-07-G-D [mm] "Samtec 100mil, 2x6, 230 mil above insulator"
  rrect6% 1.65x1.65 hole 1.016: 1(-6.35,-1.27)
  round 1.65 hole 1.016: 2(-6.35,1.27) 3(-3.81,-1.27) 4(-3.81,1.27) 5(-1.27,-1.27) 6(-1.27,1.27) 7(1.27,-1.27) 8(1.27,1.27) 9(3.81,-1.27) 10(3.81,1.27) 11(6.35,-1.27) 12(6.35,1.27)
  silkscreen extent -8.65,-2.54 7.62,2.54
WEEE_Minimum [mil] "WEEElie bin"
  silkscreen extent 22,-71 54,74
XAL7070 [mm] "COILCRAFT"
  rect 1.63x7.33 smd: 1(-2.285,0) 2(2.285,0)
  silkscreen extent -3.8,-4 3.8,4

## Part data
C1: library part CMP-0008378-2, "CAP, CERM, 10 uF, 25 V, +/- 10%, X7R, 0805"
C2: library part CMP-0010657-1, "CAP, AL, 330 uF, 25 V, +/- 20%, 0.15 ohm, SMD"
C3 C4 C5 C6 C21 C22: library part CMP-0008928-3, "CAP, CERM, 22 uF, 25 V, +/- 20%, X6S, 1206_190"
C7 C8 C32 C33: library part CMP-0086485-1, "CAP CER 1UF 25V X6S 0402"
C9: library part CMP-0007078-4, "CAP, CERM, 0.1 uF, 50 V, +/- 10%, X7R, AEC-Q200 Grade 1, 0603"
C10: library part CMP-0007370-4, "CAP, CERM, 2.2 uF, 10 V, +/- 10%, X7R, 0603"
C11 C24: library part CMP-0006623-2, "CAP, CERM, 0.1 uF, 6.3 V, +/- 10%, X7R, 0402"
C12 C13 C14 C15 C16 C25 C26 C27 C28 C29: library part CMP-0008926-3, "CAP, CERM, 47 uF, 6.3 V, +/- 10%, X6S, 1206"
C17 C30: library part CMP-0012642-3, "CAP, Tantalum Polymer, 470 uF, 6.3 V, +/- 20%, 0.01 ohm, 7343-40 SMD"
C18: library part CMP-0006983-4, "CAP, CERM, 2200 pF, 50 V, +/- 10%, X7R, 0603"
C19: library part CMP-0007038-5, "CAP, CERM, 0.22 uF, 16 V, +/- 10%, X7R, 0603"
C20: library part CMP-0006900-4, "CAP, CERM, 0.022 uF, 16 V, +/- 10%, X7R, 0603"
C23: library part CMP-0007114-5, "CAP, CERM, 1000 pF, 50 V, +/- 5%, X7R, 0603"
C31: library part CMP-0006828-4, "CAP, CERM, 0.01 uF, 16 V, +/- 10%, X7R, 0603"
FID1 FID2 FID3 FID4 FID5 FID6: library part CMP-0077181-1, "Fiducial mark.  There is nothing to buy or mount."
H1 H2 H3 H4: library part CMP-0003620-1, "Bumpon, Hemisphere, 0.44 X 0.20, Clear"
J1 J2 J3 J4: library part CMP-0074910-1, "Terminal Block, 5.08 mm, 2x1, Brass, TH"
J5: library part CMP-0075484-1, "Header, 100mil, 3x1, Gold, TH"
J6: library part CMP-0075412-2, "Header, 100mil, 6x2, Gold, TH"
L1: library part CMP-0061054-1, "Inductor, Shielded, Composite, 550 nH, 29 A, 0.00142 ohm, SMD"
L2: library part CMP-0060183-1, "Inductor, Wirewound, Ceramic, 47 nH, 0.5 A, 0.31 ohm, SMD"
LBL1: library part CMP-0003625-1, "Thermal Transfer Printable Labels, 0.650\" W x 0.200\" H - 10,000 per roll"
Logo1: library part CMP-0074838-1, "Texas Instrument Corporate Signature"
Logo2: library part CMP-0074847-1, "FCC_disclaimer"
LOGO3: library part CMP-0074844-1
Logo4: library part CMP-0074769-1
LOGO5: library part CMP-0074837-1, "IEC 61010-1 Hot Surface Warning"
NT1: library part CMP-0078142-3, "Single point connection between nets."
R1 R17: library part CMP-0016567-2, "RES, 0, 1%, 0.5 W, 1206"
R2 R7 R11: library part CMP-0023343-3, "RES, 0, 1%, 0.1 W, AEC-Q200 Grade 0, 0603"
R3 R12: library part CMP-0022324-4, "RES, 30.1 k, 1%, 0.1 W, AEC-Q200 Grade 0, 0603"
R4: library part CMP-0023931-3, "RES, 20.0 k, 0.1%, 0.1 W, 0603"
R5: library part CMP-0022558-4, "RES, 6.04 k, 1%, 0.1 W, AEC-Q200 Grade 0, 0603"
R6: library part CMP-0022098-4, "RES, 18.7 k, 1%, 0.1 W, AEC-Q200 Grade 0, 0603"
R8: library part CMP-0022003-4, "RES, 10.0, 1%, 0.1 W, AEC-Q200 Grade 0, 0603"
R9 R10: library part CMP-0021998-4, "RES, 10.0 k, 1%, 0.1 W, AEC-Q200 Grade 0, 0603"
R13: library part CMP-0023212-5, "RES, 60.4 k, 1%, 0.1 W, 0603"
R14: library part CMP-0022770-4, "RES, 121 k, 1%, 0.1 W, 0603"
R15: library part CMP-0022232-4, "RES, 243 k, 1%, 0.1 W, AEC-Q200 Grade 0, 0603"
R16: library part CMP-0018746-2, "RES, 2.2, 5%, 0.5 W, 1206"
SH-J1 SH-J2: library part CMP-0003623-3, "Shunt, 100mil, Gold plated, Black"
TP1 TP3 TP13: library part CMP-0055147-1, "Test Point, Multipurpose, Red, TH"
TP2 TP7 TP8 TP14: library part CMP-0055148-1, "Test Point, Multipurpose, Black, TH"
TP4 TP5 TP6: library part CMP-0055146-1, "Test Point, Compact, Yellow, TH"
TP9: library part CMP-0055145-1, "Test Point, Compact, Orange, TH"
TP10 TP11 TP12: library part CMP-0055150-1, "Test Point, Multipurpose, Orange, TH"
U1: library part CMP-0079178-4, "4-V to 16-V Input, 20-A Single Synchronous Step-Down Converter, RWW0021A (VQFN-HR-21)"
ZZ1: library part CMP-0003616-3
ZZ2: library part CMP-0077236-1
ZZ3: library part CMP-0077237-1
ZZ4: library part CMP-0077238-1

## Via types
v1: diameter 24, hole 12, Top Layer to Bottom Layer, tented both sides, 196 vias
v2: diameter 20, hole 10, Top Layer to Bottom Layer, tented both sides, 8 vias
v3: diameter 20, hole 8, Top Layer to Bottom Layer, tented both sides, 7 vias
v4: diameter 24, hole 10, Top Layer to Bottom Layer, tented both sides, 2 vias
v5: diameter 18, hole 8, Top Layer to Bottom Layer, tented both sides, 1 vias
v6: diameter 22, hole 12, Top Layer to Bottom Layer, tented both sides, 1 vias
